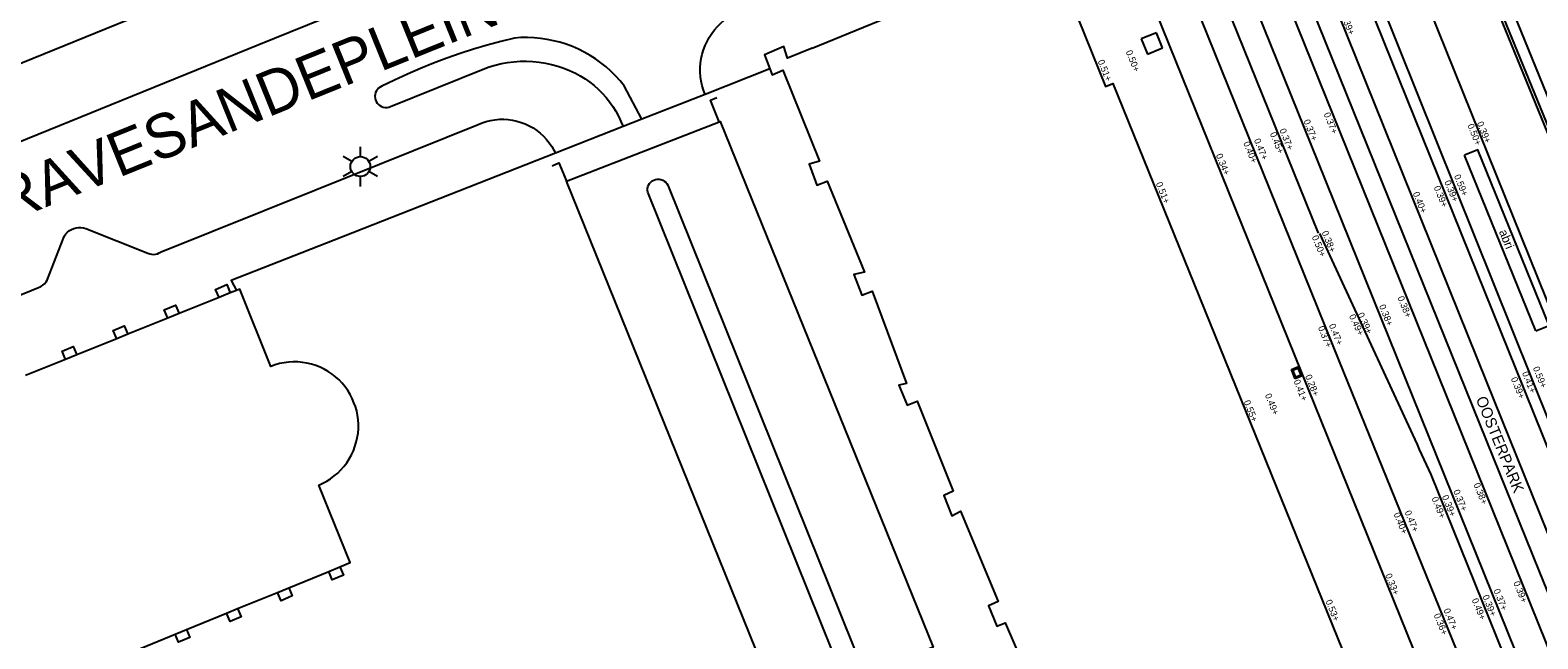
# Model space of a CAD drawing. Extents: x 122462 to 123306, y 485548 to 486417.
# Drawn here: x 122895.2 to 122963.4, y 485753.4 to 485781 of the extents above; entities that cross this region are included whole.
import ezdxf

# ---------------------------------------------------------------- set-up
doc = ezdxf.new("R2010")
doc.units = 0
for name, color, linetype in [('B-WE-OG-HOOGTEPUNT-S', 7, 'Continuous'), ('B-WE-OG-TOPOGRAFIE_RAILS-G', 7, 'Continuous'), ('B-WE-OG-TOPOGRAFIE_STRAATNAAM', 7, 'Continuous'), ('B-WE-OG-TOPOKAART-G', 7, 'Continuous'), ('B-WE-RI-HWA_KOLK-S', 7, 'Continuous'), ('B-WE-RI-HWA_RIOOLPUT-S', 7, 'Continuous'), ('B-WE-VH-KANTOPSLUITING_TROTTOIRBAND_130 150-G', 7, 'Continuous'), ('B-WE-VH-MATERIAALGRENS-G', 7, 'Continuous'), ('B-WE-VH-MATERIAALGRENS_ASFALT-G', 7, 'Continuous'), ('B-WE-VW-MARKERING_LANGS_STREEP_DOORGETROKKEN_010-G', 7, 'Continuous'), ('Level 1', 7, 'Continuous'), ('Level 17', 7, 'Continuous'), ('Level 19', 7, 'Continuous'), ('Level 21', 7, 'Continuous'), ('Level 24', 7, 'Continuous'), ('Level 45', 7, 'Continuous'), ('Level 50', 7, 'Continuous'), ('N werkgrens', 7, 'Continuous'), ('N-WE-GR-BOOM_DOORWORTELBARE RUIMTE-G', 7, 'Continuous'), ('N-WE-IE-MEUBILAIR_ABRI-S', 7, 'Continuous'), ('V markering ononderbroken streep 10 cm', 7, 'Continuous'), ('V Rails', 7, 'Continuous'), ('V-WE-GR-BOOM-S', 7, 'Continuous')]:
    doc.layers.add(name, color=color, linetype=linetype)

msp = doc.modelspace()

# ---------------------------------------------------------------- linework, layer by layer
at = {"layer": 'B-WE-OG-TOPOGRAFIE_RAILS-G'}
for points in [[(122953.448, 485775.05), (122973.836, 485724.499)], [(122954.784, 485775.587), (122975.171, 485725.04)], [(122962.418, 485765.659), (122978.277, 485726.298)], [(122961.082, 485765.121), (122976.943, 485725.757)]]:
    msp.add_lwpolyline(points, dxfattribs=at)
at = {"layer": 'B-WE-OG-TOPOKAART-G'}
msp.add_lwpolyline([(122930.558, 485780.209), (122935.952, 485782.422), (122935.762, 485782.891), (122936.616, 485783.237), (122936.805, 485782.767), (122941.366, 485784.612), (122943.842, 485778.46), (122944.174, 485778.596), (122958.027, 485744.404), (122956.235, 485743.648), (122963.319, 485726.116), (122964.959, 485726.783), (122967.006, 485721.732)], dxfattribs=at)
at = {"layer": 'B-WE-RI-HWA_KOLK-S'}
for p, q in [((122952.256, 485765.648), (122952.581, 485765.779)), ((122952.424, 485765.231), (122952.256, 485765.648)), ((122952.581, 485765.779), (122952.749, 485765.362)), ((122952.589, 485765.718), (122952.607, 485765.674)), ((122952.6, 485765.733), (122952.595, 485765.731)), ((122952.607, 485765.674), (122952.619, 485765.644)), ((122952.637, 485765.64), (122952.632, 485765.638)), ((122952.636, 485765.602), (122952.666, 485765.528)), ((122952.646, 485765.617), (122952.642, 485765.615)), ((122952.684, 485765.524), (122952.679, 485765.522)), ((122952.693, 485765.501), (122952.688, 485765.499)), ((122952.749, 485765.362), (122952.424, 485765.231)), ((122952.683, 485765.486), (122952.713, 485765.412)), ((122952.73, 485765.408), (122952.726, 485765.406))]:
    msp.add_line(p, q, dxfattribs=at)
msp.add_lwpolyline([(122952.452, 485765.296), (122952.321, 485765.621), (122952.553, 485765.714), (122952.684, 485765.389)], close=True, dxfattribs=at)
for centre, start, end in [((122952.599, 485765.722), 111.932, 201.932), ((122952.629, 485765.647), 201.932, 291.932), ((122952.645, 485765.606), 111.932, 201.932), ((122952.675, 485765.531), 201.932, 291.932), ((122952.692, 485765.49), 111.932, 201.932), ((122952.722, 485765.415), 201.932, 291.932)]:
    msp.add_arc(centre, 0.01, start, end, dxfattribs=at)
at = {"layer": 'B-WE-RI-HWA_RIOOLPUT-S'}
for p, q in [((122946.145, 485780.897), (122945.458, 485780.618)), ((122945.458, 485780.618), (122945.738, 485779.931)), ((122946.424, 485780.211), (122946.145, 485780.897)), ((122945.738, 485779.931), (122946.424, 485780.211))]:
    msp.add_line(p, q, dxfattribs=at)
at = {"layer": 'B-WE-VH-KANTOPSLUITING_TROTTOIRBAND_130 150-G'}
for points in [[(122944.788, 485793.338), (122945.622, 485791.289), (122948.972, 485782.968), (122953.472, 485771.818)], [(122944.02, 485787.037), (122960.779, 485745.561)]]:
    msp.add_lwpolyline(points, dxfattribs=at)
at = {"layer": 'B-WE-VH-MATERIAALGRENS-G'}
msp.add_lwpolyline([(122983.898, 485728.575), (122964.99, 485775.27), (122961.325, 485784.246)], dxfattribs=at)
at = {"layer": 'B-WE-VH-MATERIAALGRENS_ASFALT-G'}
msp.add_lwpolyline([(122960.723, 485784.001), (122964.388, 485775.026), (122983.295, 485728.331)], dxfattribs=at)
at = {"layer": 'B-WE-VW-MARKERING_LANGS_STREEP_DOORGETROKKEN_010-G'}
msp.add_lwpolyline([(122969.538, 485741.639), (122963.484, 485756.493), (122960.179, 485764.685)], dxfattribs=at)
at = {"layer": 'Level 1'}
for p, q in [((122903.716, 485768.915), (122901.902, 485768.182)), ((122904.213, 485769.116), (122903.716, 485768.915)), ((122904.504, 485769.233), (122904.213, 485769.116)), ((122901.397, 485767.978), (122899.581, 485767.244)), ((122901.902, 485768.182), (122901.397, 485767.978)), ((122899.077, 485767.041), (122897.27, 485766.311)), ((122899.581, 485767.244), (122899.077, 485767.041)), ((122897.27, 485766.311), (122896.761, 485766.106)), ((122896.761, 485766.106), (122894.95, 485765.374)), ((122908.679, 485756.505), (122909.184, 485756.712)), ((122906.863, 485755.762), (122908.679, 485756.505)), ((122904.553, 485754.817), (122906.35, 485755.552)), ((122906.35, 485755.552), (122906.863, 485755.762)), ((122902.24, 485753.87), (122904.046, 485754.609)), ((122904.046, 485754.609), (122904.553, 485754.817)), ((122899.928, 485752.924), (122901.731, 485753.662)), ((122901.731, 485753.662), (122902.24, 485753.87))]:
    msp.add_line(p, q, dxfattribs=at)
for points in [[(122930.558, 485780.209), (122929.442, 485779.751), (122929.272, 485780.277), (122928.4, 485779.902), (122928.648, 485779.262)], [(122928.648, 485779.262), (122928.75, 485778.996), (122929.235, 485779.21), (122930.9, 485775.083), (122930.421, 485774.955), (122930.778, 485774.002), (122931.247, 485774.183), (122932.924, 485770.062), (122932.452, 485769.947), (122932.815, 485769.018), (122933.275, 485769.192), (122934.839, 485765.016), (122934.48, 485764.942), (122934.859, 485764.029), (122935.322, 485764.211), (122936.945, 485760.133), (122936.517, 485759.942), (122936.89, 485759.024), (122937.271, 485759.236), (122938.986, 485755.143), (122938.546, 485754.942), (122938.917, 485754.022), (122939.301, 485754.177), (122941.028, 485750.138)], [(122909.184, 485756.712), (122909.647, 485756.901), (122908.221, 485760.408), (122908.408, 485760.494), (122908.589, 485760.592), (122908.763, 485760.703), (122908.928, 485760.826), (122909.084, 485760.961), (122909.23, 485761.106), (122909.366, 485761.261), (122909.49, 485761.425), (122909.603, 485761.598), (122909.703, 485761.778), (122909.79, 485761.965), (122909.864, 485762.157), (122909.924, 485762.354), (122909.969, 485762.555), (122910.001, 485762.758), (122910.018, 485762.964), (122910.021, 485763.169), (122910.009, 485763.375), (122909.983, 485763.579), (122909.943, 485763.781), (122909.888, 485763.98), (122909.819, 485764.139), (122909.738, 485764.331), (122909.644, 485764.516), (122909.537, 485764.694), (122909.417, 485764.864), (122909.285, 485765.024), (122909.142, 485765.175), (122908.988, 485765.315), (122908.825, 485765.444), (122908.652, 485765.56), (122908.472, 485765.663), (122908.285, 485765.754), (122908.092, 485765.83), (122907.893, 485765.892), (122907.691, 485765.94), (122907.486, 485765.973), (122907.279, 485765.991), (122907.071, 485765.995), (122906.863, 485765.983), (122906.657, 485765.956), (122906.454, 485765.914), (122906.253, 485765.858), (122906.058, 485765.787), (122904.655, 485769.294), (122904.504, 485769.233)]]:
    msp.add_lwpolyline(points, dxfattribs=at)
at = {"layer": 'Level 17'}
for points in [[(122870.514, 485769.768), (122870.62, 485769.769), (122870.726, 485769.782), (122870.83, 485769.806), (122870.931, 485769.841), (122871.027, 485769.886), (122904.324, 485783.439), (122911.897, 485786.521), (122912.102, 485786.622), (122912.299, 485786.735), (122912.49, 485786.861), (122912.672, 485786.998), (122912.845, 485787.146), (122913.009, 485787.305), (122913.162, 485787.474)], [(122913.462, 485783.58), (122905.513, 485780.351), (122865.539, 485764.111)], [(122925.713, 485778.108), (122925.641, 485778.302), (122925.584, 485778.5), (122925.541, 485778.702), (122925.512, 485778.907), (122925.498, 485779.113), (122925.498, 485779.32), (122925.513, 485779.526), (122925.543, 485779.73), (122925.587, 485779.932), (122925.646, 485780.13), (122925.718, 485780.324), (122925.804, 485780.512), (122925.903, 485780.693), (122926.015, 485780.867), (122926.139, 485781.033), (122926.274, 485781.189), (122926.42, 485781.335), (122926.576, 485781.47), (122926.741, 485781.594), (122926.915, 485781.706), (122927.096, 485781.806), (122927.284, 485781.892), (122929.513, 485782.79)], [(122922.85, 485776.983), (122922.051, 485778.499), (122921.863, 485778.729), (122921.663, 485778.949), (122921.451, 485779.159), (122921.229, 485779.356), (122920.996, 485779.542), (122920.755, 485779.715), (122920.504, 485779.875), (122920.245, 485780.022), (122919.979, 485780.155), (122919.706, 485780.274), (122919.427, 485780.378), (122919.144, 485780.467), (122918.856, 485780.541), (122918.564, 485780.6), (122918.27, 485780.643), (122917.974, 485780.671), (122917.676, 485780.683), (122917.379, 485780.679), (122917.082, 485780.66), (122916.461, 485780.505), (122915.844, 485780.335), (122915.231, 485780.152), (122914.622, 485779.954), (122914.018, 485779.743), (122913.419, 485779.517), (122912.826, 485779.278), (122912.238, 485779.026), (122911.656, 485778.759), (122911.08, 485778.48), (122911.003, 485778.441), (122910.934, 485778.39), (122910.883, 485778.337), (122910.835, 485778.268), (122910.799, 485778.192), (122910.776, 485778.111), (122910.767, 485778.027), (122910.773, 485777.943), (122910.792, 485777.861), (122910.825, 485777.784), (122910.87, 485777.713), (122910.927, 485777.651), (122910.993, 485777.599), (122911.067, 485777.559), (122911.147, 485777.532), (122911.23, 485777.519), (122911.314, 485777.519), (122911.397, 485777.534), (122911.476, 485777.563), (122915.669, 485779.259), (122915.939, 485779.356), (122916.213, 485779.438), (122916.492, 485779.505), (122916.774, 485779.556), (122917.059, 485779.591), (122917.345, 485779.61), (122917.632, 485779.613), (122917.918, 485779.601), (122918.203, 485779.572), (122918.486, 485779.528), (122918.767, 485779.468), (122919.043, 485779.393), (122919.315, 485779.302), (122919.582, 485779.196), (122919.842, 485779.076), (122920.066, 485778.952), (122920.282, 485778.816), (122920.49, 485778.669), (122920.69, 485778.509), (122920.881, 485778.339), (122921.061, 485778.158), (122921.231, 485777.967), (122921.39, 485777.767), (122921.538, 485777.558), (122921.673, 485777.342), (122921.796, 485777.118), (122921.907, 485776.887), (122922.004, 485776.651)], [(122868.781, 485758.44), (122895.541, 485769.368), (122895.637, 485769.41), (122895.727, 485769.465), (122895.807, 485769.533), (122895.876, 485769.612), (122895.933, 485769.7), (122896.663, 485771.603), (122896.715, 485771.7), (122896.779, 485771.789), (122896.855, 485771.868), (122896.94, 485771.937), (122897.035, 485771.993), (122897.135, 485772.036), (122897.241, 485772.065), (122897.35, 485772.08), (122897.46, 485772.08), (122897.568, 485772.065), (122897.674, 485772.036), (122900.487, 485770.92), (122900.571, 485770.889), (122900.658, 485770.87), (122900.748, 485770.865), (122900.837, 485770.873), (122900.924, 485770.895), (122901.006, 485770.929), (122901.083, 485770.975), (122908.047, 485773.775), (122915.435, 485776.745), (122915.62, 485776.821), (122915.81, 485776.883), (122916.004, 485776.93), (122916.201, 485776.963), (122916.4, 485776.981), (122916.6, 485776.983), (122916.8, 485776.971), (122916.998, 485776.943), (122917.193, 485776.9), (122917.384, 485776.843), (122917.571, 485776.772), (122917.752, 485776.686), (122917.926, 485776.588), (122918.091, 485776.476), (122918.248, 485776.352), (122918.395, 485776.217), (122918.532, 485776.071), (122918.657, 485775.915), (122918.77, 485775.75), (122918.87, 485775.577), (122918.936, 485775.445)]]:
    msp.add_lwpolyline(points, dxfattribs=at)
at = {"layer": 'Level 19'}
msp.add_lwpolyline([(122932.058, 485751.455), (122923.122, 485773.676), (122923.109, 485773.758), (122923.11, 485773.842), (122923.125, 485773.924), (122923.155, 485774.002), (122923.197, 485774.074), (122923.252, 485774.137), (122923.316, 485774.19), (122923.389, 485774.231), (122923.468, 485774.259), (122923.55, 485774.273), (122923.634, 485774.272), (122923.716, 485774.257), (122923.794, 485774.228), (122923.866, 485774.185), (122923.93, 485774.131), (122923.983, 485774.067), (122924.024, 485773.994), (122932.945, 485751.816)], dxfattribs=at)
at = {"layer": 'Level 21'}
for points in [[(122903.716, 485768.915), (122903.556, 485769.277), (122904.06, 485769.497), (122904.213, 485769.116)], [(122901.397, 485767.978), (122901.231, 485768.352), (122901.746, 485768.561), (122901.902, 485768.182)], [(122899.077, 485767.041), (122898.917, 485767.416), (122899.42, 485767.62), (122899.581, 485767.244)], [(122896.761, 485766.106), (122896.604, 485766.48), (122897.111, 485766.685), (122897.27, 485766.311)], [(122909.184, 485756.712), (122909.34, 485756.33), (122908.835, 485756.124), (122908.679, 485756.505)], [(122906.863, 485755.762), (122907.026, 485755.397), (122906.52, 485755.171), (122906.35, 485755.552)], [(122904.553, 485754.817), (122904.71, 485754.449), (122904.206, 485754.234), (122904.046, 485754.609)], [(122902.24, 485753.87), (122902.387, 485753.509), (122901.877, 485753.302), (122901.731, 485753.662)]]:
    msp.add_lwpolyline(points, dxfattribs=at)
at = {"layer": 'Level 24'}
for points in [[(122926.355, 485776.867), (122925.957, 485777.843), (122926.246, 485777.961)], [(122918.794, 485774.874), (122919.095, 485775.002), (122919.436, 485774.172)]]:
    msp.add_lwpolyline(points, dxfattribs=at)
at = {"layer": 'Level 45'}
msp.add_lwpolyline([(122929.116, 485750.257), (122919.436, 485774.172), (122926.392, 485776.882), (122936.039, 485753.076), (122935.894, 485753.017), (122929.116, 485750.257)], dxfattribs=at)
at = {"layer": 'Level 50'}
for p, q in [((122910.109, 485775.29), (122910.109, 485775.74)), ((122909.719, 485775.065), (122909.329, 485775.29)), ((122910.888, 485775.29), (122910.498, 485775.065)), ((122909.719, 485774.615), (122909.329, 485774.39)), ((122910.109, 485773.94), (122910.109, 485774.39)), ((122910.888, 485774.39), (122910.498, 485774.615))]:
    msp.add_line(p, q, dxfattribs=at)
msp.add_circle((122910.109, 485774.84), 0.45, dxfattribs=at)
at = {"layer": 'N werkgrens'}
for p, q in [((122928.648, 485779.262), (122925.713, 485778.108)), ((122925.713, 485778.108), (122922.85, 485776.983)), ((122922.004, 485776.651), (122918.936, 485775.445)), ((122922.85, 485776.983), (122922.004, 485776.651))]:
    msp.add_line(p, q, dxfattribs=at)
msp.add_lwpolyline([(122918.936, 485775.445), (122908.92, 485771.508), (122904.257, 485769.675), (122904.504, 485769.233)], dxfattribs=at)
at = {"layer": 'N-WE-IE-MEUBILAIR_ABRI-S'}
msp.add_line((122963.322, 485767.404), (122960.1, 485775.357), dxfattribs=at)
msp.add_lwpolyline([(122963.322, 485767.404), (122963.924, 485767.648), (122960.701, 485775.601), (122960.1, 485775.357)], dxfattribs=at)
at = {"layer": 'V markering ononderbroken streep 10 cm'}
msp.add_lwpolyline([(122960.179, 485764.685), (122947.097, 485797.105)], dxfattribs=at)
at = {"layer": 'V Rails'}
for points in [[(122926.135, 485842.678), (122941.546, 485804.559), (122953.448, 485775.05)], [(122927.47, 485843.218), (122942.882, 485805.099), (122954.784, 485775.587)], [(122936.708, 485829.325), (122946.878, 485804.229), (122962.418, 485765.659)], [(122935.374, 485828.785), (122945.542, 485803.689), (122961.082, 485765.121)]]:
    msp.add_lwpolyline(points, dxfattribs=at)
at = {"layer": 'V-WE-GR-BOOM-S'}
for points in [[(122951.74, 485798.736), (122953.069, 485795.465), (122953.163, 485795.502), (122953.521, 485794.633), (122953.438, 485794.593), (122954.14, 485792.811), (122957.738, 485783.873), (122965.696, 485764.131), (122970.276, 485752.884), (122971.001, 485751.054), (122971.388, 485750.095)], [(122969.614, 485749.271), (122963.986, 485763.138), (122956.242, 485782.448), (122949.942, 485798.01)], [(122962.728, 485745.564), (122954.408, 485766.082), (122945.68, 485787.702)], [(122983.435, 485728.388), (122964.527, 485775.082), (122960.862, 485784.057)], [(122953.523, 485771.807), (122957.738, 485762.699)], [(122958.571, 485760.89), (122964.195, 485746.938)]]:
    msp.add_lwpolyline(points, dxfattribs=at)
msp.add_arc((123088.765, 485821.938), 143.796, 204.32813, 205.12168, dxfattribs=at)

# ---------------------------------------------------------------- texts
at = {"layer": 'B-WE-OG-HOOGTEPUNT-S'}
for s, rotation, p in [('0.39+', 292.0562, (122954.48, 485781.706)), ('0.50+', 292.0015, (122944.752, 485780.04)), ('0.51+', 292.0015, (122943.484, 485779.612)), ('0.37+', 292.0562, (122953.714, 485777.223)), ('0.37+', 292.0562, (122951.708, 485776.494)), ('0.37+', 292.0562, (122952.795, 485776.906)), ('0.50+', 292.0562, (122960.216, 485776.709)), ('0.39+', 292.0562, (122960.648, 485776.81)), ('0.40+', 292.0562, (122950.071, 485775.906)), ('0.47+', 292.0562, (122950.552, 485776.04)), ('0.45+', 292.0562, (122951.277, 485776.332)), ('0.34+', 292.0015, (122948.832, 485775.357)), ('0.59+', 292.0562, (122959.612, 485774.414)), ('0.51+', 292.0015, (122946.112, 485774.071)), ('0.40+', 292.0562, (122957.746, 485773.63)), ('0.39+', 292.0562, (122958.695, 485773.901)), ('0.39+', 292.0562, (122959.176, 485774.149)), ('0.50+', 292.0562, (122953.175, 485771.657)), ('0.38+', 292.0562, (122953.622, 485771.861)), ('0.38+', 291.9741, (122957.053, 485768.904)), ('0.39+', 295.1251, (122955.238, 485768.146)), ('0.38+', 291.9741, (122956.217, 485768.526)), ('0.37+', 292.0458, (122953.454, 485767.551)), ('0.47+', 292.0458, (122953.948, 485767.654)), ('0.49+', 295.1251, (122954.858, 485768.068)), ('0.41+', 292.0458, (122962.692, 485765.489)), ('0.59+', 292.0458, (122963.182, 485765.715)), ('0.41+', 292.0015, (122952.347, 485765.124)), ('0.28+', 292.0015, (122952.873, 485765.349)), ('0.39+', 292.0458, (122962.187, 485765.235)), ('0.55+', 292.0015, (122950.089, 485764.188)), ('0.49+', 292.0015, (122951.05, 485764.492)), ('0.37+', 292.0458, (122959.578, 485760.14)), ('0.38+', 292.0458, (122960.494, 485760.443)), ('0.49+', 292.0458, (122958.597, 485759.815)), ('0.39+', 292.0458, (122959.065, 485759.894)), ('0.40+', 292.0458, (122956.877, 485759.102)), ('0.47+', 292.0458, (122957.376, 485759.195)), ('0.33+', 292.0015, (122956.499, 485756.34)), ('0.39+', 292.0458, (122962.297, 485755.992)), ('0.49+', 292.0458, (122960.416, 485755.217)), ('0.39+', 292.0458, (122960.897, 485755.377)), ('0.37+', 292.0458, (122961.395, 485755.645)), ('0.53+', 292.0015, (122953.793, 485755.155)), ('0.36+', 292.0458, (122958.692, 485754.53)), ('0.47+', 292.0458, (122959.136, 485754.759))]:
    msp.add_text(s, height=0.3, rotation=rotation, dxfattribs=at).set_placement(p)
at = {"layer": 'B-WE-OG-TOPOGRAFIE_STRAATNAAM'}
msp.add_text('OOSTERPARK', height=0.5, rotation=292.0555, dxfattribs=at).set_placement((122960.598, 485764.316))
at = {"layer": 'N-WE-GR-BOOM_DOORWORTELBARE RUIMTE-G'}
msp.add_text("'S-GRAVESANDEPLEIN", height=2, rotation=22.03547, dxfattribs=at).set_placement((122889.186, 485770.287))
at = {"layer": 'N-WE-IE-MEUBILAIR_ABRI-S'}
msp.add_text('abri', height=0.4, rotation=292.05508, dxfattribs=at).set_placement((122961.646, 485771.893))

doc.saveas('drawing.dxf')
